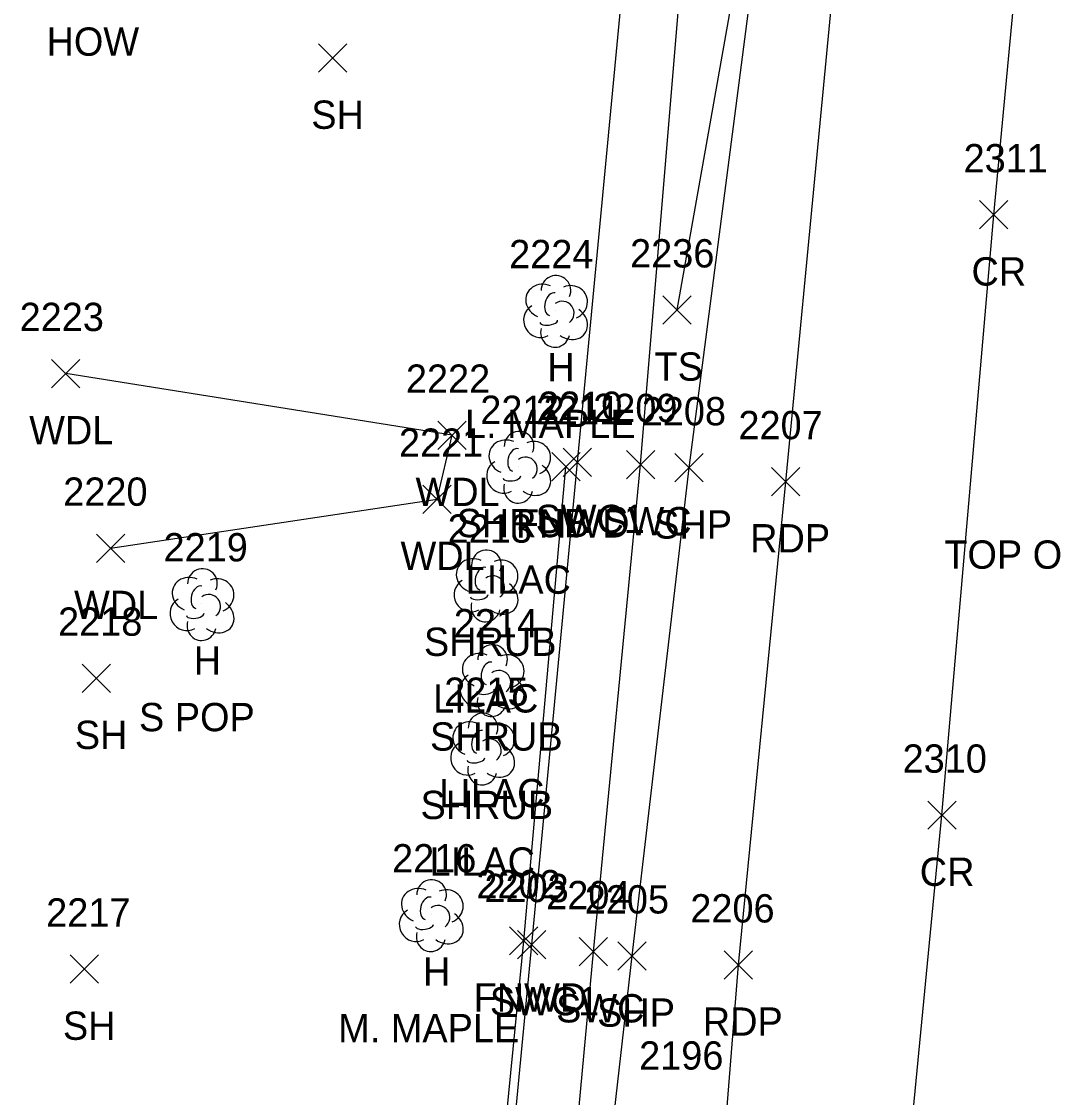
# Model space of a CAD drawing. Extents: x 1653908 to 1654393, y 539913 to 544256.
# Drawn here: x 1654041.3 to 1654114.5, y 542020.2 to 542096.3 of the extents above; entities that cross this region are included whole.
import ezdxf

# ---------------------------------------------------------------- set-up
doc = ezdxf.new("R2010")
doc.units = 0
for name, color, linetype in [('C_C', 7, 'Continuous'), ('L_A', 7, 'Continuous'), ('L_C', 7, 'Continuous'), ('L_I', 7, 'Continuous'), ('L_TIC', 7, 'Continuous'), ('LAWA', 7, 'Continuous'), ('LELB', 7, 'Continuous'), ('LFNC', 7, 'Continuous'), ('LSH', 7, 'Continuous'), ('LTD', 7, 'Continuous'), ('P_A', 7, 'Continuous'), ('P_I', 7, 'Continuous'), ('P_TIC', 7, 'Continuous'), ('PET', 7, 'Continuous'), ('PRC', 7, 'Continuous'), ('PSP', 7, 'Continuous'), ('R_A', 7, 'Continuous'), ('R_I', 7, 'Continuous'), ('R_TIC', 7, 'Continuous'), ('RSW', 7, 'Continuous'), ('U_I', 7, 'Continuous')]:
    doc.layers.add(name, color=color, linetype=linetype)

msp = doc.modelspace()

# ---------------------------------------------------------------- linework, layer by layer
at = {"layer": 'L_TIC'}
for points in [[(1654062.306, 542092.685), (1654064.306, 542094.685)], [(1654064.306, 542092.685), (1654062.306, 542094.685)], [(1654086.622, 542074.889), (1654088.622, 542076.889)], [(1654088.622, 542074.889), (1654086.622, 542076.889)], [(1654043.459, 542070.396), (1654045.459, 542072.396)], [(1654045.459, 542070.396), (1654043.459, 542072.396)], [(1654070.737, 542066.034), (1654072.737, 542068.034)], [(1654072.737, 542066.034), (1654070.737, 542068.034)], [(1654078.779, 542063.807), (1654080.779, 542065.807)], [(1654080.779, 542063.807), (1654078.779, 542065.807)], [(1654069.679, 542061.512), (1654071.679, 542063.512)], [(1654071.679, 542061.512), (1654069.679, 542063.512)], [(1654046.627, 542058.05), (1654048.627, 542060.05)], [(1654048.627, 542058.05), (1654046.627, 542060.05)], [(1654045.609, 542048.866), (1654047.609, 542050.866)], [(1654047.609, 542048.866), (1654045.609, 542050.866)], [(1654075.792, 542030.31), (1654077.792, 542032.31)], [(1654077.792, 542030.31), (1654075.792, 542032.31)], [(1654044.768, 542028.315), (1654046.768, 542030.315)], [(1654046.768, 542028.315), (1654044.768, 542030.315)]]:
    msp.add_lwpolyline(points, dxfattribs=at)
at = {"layer": 'LAWA'}
msp.add_lwpolyline([(1654047.627, 542059.05), (1654070.679, 542062.512), (1654071.737, 542067.034), (1654044.459, 542071.396)], dxfattribs=at)
at = {"layer": 'LELB'}
msp.add_lwpolyline([(1654087.622, 542075.889), (1654092.617, 542104.059), (1654093.803, 542115.245), (1654095.73, 542154.4)], dxfattribs=at)
at = {"layer": 'LFNC'}
msp.add_lwpolyline([(1654072.393, 541986.583), (1654076.792, 542031.31), (1654079.779, 542064.807)], dxfattribs=at)
at = {"layer": 'LSH'}
for p, q in [((1654076.422, 542064.831), (1654076.422, 542064.831)), ((1654076.422, 542064.831), (1654076.422, 542064.831)), ((1654074.118, 542056.442), (1654074.118, 542056.442)), ((1654074.118, 542056.442), (1654074.118, 542056.442)), ((1654074.55, 542049.75), (1654074.55, 542049.75)), ((1654074.55, 542049.75), (1654074.55, 542049.75)), ((1654073.877, 542044.913), (1654073.877, 542044.913)), ((1654073.877, 542044.913), (1654073.877, 542044.913))]:
    msp.add_line(p, q, dxfattribs=at)
for centre in [(1654076.469, 542066.265), (1654074.165, 542057.876), (1654074.597, 542051.184), (1654073.924, 542046.347)]:
    msp.add_arc(centre, 1.047, 335.52715, 180.95627, dxfattribs=at)
for centre, major_axis, ratio, start_param, end_param in [((1654075.631, 542065.498), (1.21, -0.512), 0.895232, 1.570796, 4.712389), ((1654077.464, 542065.415), (-1.141, -0.483), 0.949671, 1.570796, 4.712389), ((1654076.214, 542065.29), (-0.208, -0.792), 0.645439, 3.141593, 6.283185), ((1654075.339, 542064.123), (0.584, -1.042), 0.959034, 3.141593, 6.283185), ((1654076.922, 542064.665), (-0.5, 0.667), 0.989748, 3.141593, 6.283185), ((1654077.422, 542063.998), (-1.09, 0.792), 0.841452, 1.570796, 4.712389), ((1654075.964, 542064.081), (-0.625, -0.083), 0.423636, 0, 3.141593), ((1654076.423, 542063.331), (0.265, 1.061), 0.942809, 1.570796, 4.712389), ((1654073.326, 542057.109), (1.21, -0.512), 0.895232, 1.570796, 4.712389), ((1654075.16, 542057.026), (-1.141, -0.483), 0.949671, 1.570796, 4.712389), ((1654073.91, 542056.901), (-0.208, -0.792), 0.645439, 3.141593, 6.283185), ((1654073.035, 542055.734), (0.584, -1.042), 0.959034, 3.141593, 6.283185), ((1654074.618, 542056.276), (-0.5, 0.667), 0.989748, 3.141593, 6.283185), ((1654075.118, 542055.609), (-1.09, 0.792), 0.841452, 1.570796, 4.712389), ((1654073.66, 542055.692), (-0.625, -0.083), 0.423636, 0, 3.141593), ((1654074.118, 542054.942), (0.265, 1.061), 0.942809, 1.570796, 4.712389), ((1654073.758, 542050.417), (1.21, -0.512), 0.895232, 1.570796, 4.712389), ((1654075.592, 542050.334), (-1.141, -0.483), 0.949671, 1.570796, 4.712389), ((1654074.342, 542050.208), (-0.208, -0.792), 0.645439, 3.141593, 6.283185), ((1654073.467, 542049.042), (0.584, -1.042), 0.959034, 3.141593, 6.283185), ((1654075.05, 542049.584), (-0.5, 0.667), 0.989748, 3.141593, 6.283185), ((1654075.55, 542048.917), (-1.09, 0.792), 0.841452, 1.570796, 4.712389), ((1654074.55, 542048.25), (0.265, 1.061), 0.942809, 1.570796, 4.712389), ((1654074.092, 542049), (-0.625, -0.083), 0.423636, 0, 3.141593), ((1654073.085, 542045.58), (1.21, -0.512), 0.895232, 1.570796, 4.712389), ((1654073.669, 542045.372), (-0.208, -0.792), 0.645439, 3.141593, 6.283185), ((1654074.919, 542045.497), (-1.141, -0.483), 0.949671, 1.570796, 4.712389), ((1654074.377, 542044.747), (-0.5, 0.667), 0.989748, 3.141593, 6.283185), ((1654072.794, 542044.205), (0.584, -1.042), 0.959034, 3.141593, 6.283185), ((1654074.877, 542044.08), (-1.09, 0.792), 0.841452, 1.570796, 4.712389), ((1654073.419, 542044.163), (-0.625, -0.083), 0.423636, 0, 3.141593), ((1654073.877, 542043.413), (0.265, 1.061), 0.942809, 1.570796, 4.712389)]:
    msp.add_ellipse(centre, major_axis=major_axis, ratio=ratio, start_param=start_param, end_param=end_param, dxfattribs=at)
at = {"layer": 'LTD'}
for p, q in [((1654079.025, 542075.837), (1654079.025, 542075.837)), ((1654079.025, 542075.837), (1654079.025, 542075.837)), ((1654054.061, 542055.121), (1654054.061, 542055.121)), ((1654054.061, 542055.121), (1654054.061, 542055.121)), ((1654070.248, 542033.143), (1654070.248, 542033.143)), ((1654070.248, 542033.143), (1654070.248, 542033.143))]:
    msp.add_line(p, q, dxfattribs=at)
for centre in [(1654079.072, 542077.271), (1654054.108, 542056.555), (1654070.295, 542034.577)]:
    msp.add_arc(centre, 1.047, 335.52715, 180.95627, dxfattribs=at)
for centre, major_axis, ratio, start_param, end_param in [((1654078.233, 542076.504), (1.21, -0.512), 0.895232, 1.570796, 4.712389), ((1654080.067, 542076.42), (-1.141, -0.483), 0.949671, 1.570796, 4.712389), ((1654078.817, 542076.295), (-0.208, -0.792), 0.645439, 3.141593, 6.283185), ((1654079.525, 542075.67), (-0.5, 0.667), 0.989748, 3.141593, 6.283185), ((1654077.942, 542075.128), (0.584, -1.042), 0.959034, 3.141593, 6.283185), ((1654080.025, 542075.004), (-1.09, 0.792), 0.841452, 1.570796, 4.712389), ((1654078.567, 542075.087), (-0.625, -0.083), 0.423636, 0, 3.141593), ((1654079.025, 542074.337), (0.265, 1.061), 0.942809, 1.570796, 4.712389), ((1654053.269, 542055.788), (1.21, -0.512), 0.895232, 1.570796, 4.712389), ((1654055.103, 542055.705), (-1.141, -0.483), 0.949671, 1.570796, 4.712389), ((1654053.853, 542055.58), (-0.208, -0.792), 0.645439, 3.141593, 6.283185), ((1654052.978, 542054.413), (0.584, -1.042), 0.959034, 3.141593, 6.283185), ((1654054.561, 542054.955), (-0.5, 0.667), 0.989748, 3.141593, 6.283185), ((1654055.061, 542054.288), (-1.09, 0.792), 0.841452, 1.570796, 4.712389), ((1654054.061, 542053.621), (0.265, 1.061), 0.942809, 1.570796, 4.712389), ((1654053.603, 542054.371), (-0.625, -0.083), 0.423636, 0, 3.141593), ((1654069.456, 542033.81), (1.21, -0.512), 0.895232, 1.570796, 4.712389), ((1654071.29, 542033.727), (-1.141, -0.483), 0.949671, 1.570796, 4.712389), ((1654070.04, 542033.602), (-0.208, -0.792), 0.645439, 3.141593, 6.283185), ((1654069.165, 542032.435), (0.584, -1.042), 0.959034, 3.141593, 6.283185), ((1654070.748, 542032.977), (-0.5, 0.667), 0.989748, 3.141593, 6.283185), ((1654071.248, 542032.31), (-1.09, 0.792), 0.841452, 1.570796, 4.712389), ((1654069.79, 542032.393), (-0.625, -0.083), 0.423636, 0, 3.141593), ((1654070.248, 542031.643), (0.265, 1.061), 0.942809, 1.570796, 4.712389)]:
    msp.add_ellipse(centre, major_axis=major_axis, ratio=ratio, start_param=start_param, end_param=end_param, dxfattribs=at)
at = {"layer": 'P_TIC'}
for points in [[(1654108.98, 542081.612), (1654110.98, 542083.612)], [(1654110.98, 542081.612), (1654108.98, 542083.612)], [(1654087.468, 542063.733), (1654089.468, 542065.733)], [(1654089.468, 542063.733), (1654087.468, 542065.733)], [(1654094.296, 542062.753), (1654096.296, 542064.753)], [(1654096.296, 542062.753), (1654094.296, 542064.753)], [(1654105.328, 542039.19), (1654107.328, 542041.19)], [(1654107.328, 542039.19), (1654105.328, 542041.19)], [(1654083.441, 542029.241), (1654085.441, 542031.241)], [(1654085.441, 542029.241), (1654083.441, 542031.241)], [(1654090.953, 542028.606), (1654092.953, 542030.606)], [(1654092.953, 542028.606), (1654090.953, 542030.606)]]:
    msp.add_lwpolyline(points, dxfattribs=at)
at = {"layer": 'PET'}
msp.add_lwpolyline([(1654079.776, 541659.551), (1654071.378, 541669.623), (1654062.104, 541680.771), (1654062.282, 541682.129), (1654062.946, 541688.197), (1654063.578, 541697.883), (1654065.97, 541728.278), (1654069.389, 541768.376), (1654071.189, 541795.88), (1654073.496, 541821.499), (1654077.02, 541859.137), (1654082.158, 541914.04), (1654084.92, 541947.882), (1654085.876, 541956.638), (1654088.374, 541984.799), (1654091.953, 542029.606), (1654095.296, 542063.753), (1654100.144, 542114.452), (1654103.127, 542154.148), (1654108.142, 542200.441), (1654110.744, 542235.382)], dxfattribs=at)
at = {"layer": 'PRC'}
msp.add_lwpolyline([(1654071.378, 541669.623), (1654074.689, 541707.082), (1654077.078, 541730.589), (1654080.001, 541762.219), (1654083.127, 541795.122), (1654087.252, 541836.363), (1654090.634, 541873.535), (1654094.478, 541915.806), (1654096.589, 541938.824), (1654100.212, 541977.673), (1654102.082, 541996.315), (1654106.328, 542040.19), (1654109.98, 542082.612), (1654113.749, 542122.62), (1654117.046, 542159.879), (1654120.869, 542199.278), (1654124.055, 542234.043)], dxfattribs=at)
at = {"layer": 'PSP'}
msp.add_lwpolyline([(1654078.768, 541955.953), (1654079.331, 541984.914), (1654082.059, 542009.116), (1654084.441, 542030.241), (1654088.468, 542064.733), (1654094.987, 542114.991), (1654098.586, 542154.95), (1654100.359, 542172.127), (1654102.929, 542200.545), (1654105.588, 542231.12), (1654106.164, 542236.318)], dxfattribs=at)
at = {"layer": 'R_TIC'}
for points in [[(1654079.591, 542064.121), (1654081.591, 542066.121)], [(1654081.591, 542064.121), (1654079.591, 542066.121)], [(1654084.047, 542063.963), (1654086.047, 542065.963)], [(1654086.047, 542063.963), (1654084.047, 542065.963)], [(1654076.364, 542030.045), (1654078.364, 542032.045)], [(1654078.364, 542030.045), (1654076.364, 542032.045)], [(1654080.721, 542029.543), (1654082.721, 542031.543)], [(1654082.721, 542029.543), (1654080.721, 542031.543)]]:
    msp.add_lwpolyline(points, dxfattribs=at)
at = {"layer": 'RSW'}
for points in [[(1654051.369, 541872.293), (1654052.464, 541871.499), (1654066.158, 541870.168), (1654068.181, 541915.934), (1654069.752, 541944.224), (1654070.309, 541953.544), (1654072.786, 541983.023), (1654073.085, 541986.245), (1654077.364, 542031.045), (1654080.591, 542065.121), (1654085.441, 542116.233), (1654086.206, 542120.499), (1654089.265, 542157.544), (1654090.309, 542166.745), (1654093.111, 542195.966), (1654093.599, 542201.464), (1654097.177, 542235.397)], [(1654068.64, 541821.643), (1654069.31, 541838.709), (1654070.517, 541867.733), (1654072.547, 541915.286), (1654073.845, 541942.175), (1654076.05, 541941.955), (1654076.979, 541955.526), (1654075.171, 541955.835), (1654077.56, 541985.558), (1654081.721, 542030.543), (1654085.047, 542064.963), (1654089.266, 542115.614), (1654093.425, 542156.154), (1654094.753, 542169.002), (1654097.803, 542199.999), (1654101.289, 542234.246)]]:
    msp.add_lwpolyline(points, dxfattribs=at)

# ---------------------------------------------------------------- texts
at = {"layer": 'C_C'}
msp.add_text('TOP OF NORTHERLY BOLT ON TOP', height=2, dxfattribs=at).set_placement((1654106.495, 542057.604))
at = {"layer": 'L_A'}
for s, p in [('HOW', (1654043.1, 542093.85)), ('SH', (1654061.794, 542088.685)), ('H', (1654078.458, 542070.837)), ('TS', (1654086.032, 542070.889)), ('WDL', (1654041.877, 542066.396)), ('WDL', (1654069.155, 542062.034)), ('SHRUB', (1654072.052, 542059.831)), ('FNWD', (1654076.244, 542059.807)), ('WDL', (1654068.097, 542057.512)), ('WDL', (1654045.044, 542054.05)), ('SHRUB', (1654069.748, 542051.442)), ('H', (1654053.494, 542050.121)), ('SH', (1654045.097, 542044.866)), ('SHRUB', (1654070.18, 542044.75)), ('SHRUB', (1654069.507, 542039.913)), ('H', (1654069.681, 542028.143)), ('FNWD', (1654073.256, 542026.31)), ('SH', (1654044.256, 542024.315))]:
    msp.add_text(s, height=2, dxfattribs=at).set_placement(p)
at = {"layer": 'L_C'}
for s, p in [('L. MAPLE', (1654072.647, 542066.837)), ('LILAC', (1654072.698, 542055.831)), ('LILAC', (1654070.394, 542047.442)), ('S POP', (1654049.628, 542046.121)), ('LILAC', (1654070.826, 542040.75)), ('LILAC', (1654070.153, 542035.913)), ('M. MAPLE', (1654063.697, 542024.143))]:
    msp.add_text(s, height=2, dxfattribs=at).set_placement(p)
at = {"layer": 'L_I'}
for s, p in [('2224', (1654075.765, 542078.837)), ('2236', (1654084.307, 542078.889)), ('2223', (1654041.2, 542074.396)), ('2222', (1654068.477, 542070.034)), ('2212', (1654073.73, 542067.831)), ('2211', (1654077.653, 542067.807)), ('2221', (1654067.987, 542065.512)), ('2220', (1654044.28, 542062.05)), ('2213', (1654071.425, 542059.442)), ('2219', (1654051.361, 542058.121)), ('2218', (1654043.916, 542052.866)), ('2214', (1654071.857, 542052.75)), ('2215', (1654071.184, 542047.913)), ('2216', (1654067.5, 542036.143)), ('2202', (1654073.453, 542034.31)), ('2217', (1654043.075, 542032.315))]:
    msp.add_text(s, height=2, dxfattribs=at).set_placement(p)
at = {"layer": 'P_A'}
for s, p in [('CR', (1654108.413, 542077.612)), ('SHP', (1654086.003, 542059.733)), ('RDP', (1654092.784, 542058.753)), ('CR', (1654104.761, 542035.19)), ('SHP', (1654081.977, 542025.241)), ('RDP', (1654089.441, 542024.606))]:
    msp.add_text(s, height=2, dxfattribs=at).set_placement(p)
at = {"layer": 'P_I'}
for s, p in [('2311', (1654107.855, 542085.612)), ('2208', (1654085.129, 542067.733)), ('2207', (1654091.958, 542066.753)), ('2310', (1654103.549, 542043.19)), ('2205', (1654081.103, 542033.241)), ('2206', (1654088.56, 542032.606))]:
    msp.add_text(s, height=2, dxfattribs=at).set_placement(p)
at = {"layer": 'R_A'}
for s, p in [('SWC1', (1654077.63, 542060.121)), ('SWC', (1654082.409, 542059.963)), ('SWC1', (1654074.403, 542026.045)), ('SWC', (1654079.083, 542025.543))]:
    msp.add_text(s, height=2, dxfattribs=at).set_placement(p)
at = {"layer": 'R_I'}
for s, p in [('2210', (1654077.811, 542068.121)), ('2209', (1654081.7, 542067.963)), ('2203', (1654074.025, 542034.045)), ('2204', (1654078.383, 542033.543))]:
    msp.add_text(s, height=2, dxfattribs=at).set_placement(p)
at = {"layer": 'U_I'}
msp.add_text('2196', height=2, dxfattribs=at).set_placement((1654084.946, 542022.211))

doc.saveas('drawing.dxf')
